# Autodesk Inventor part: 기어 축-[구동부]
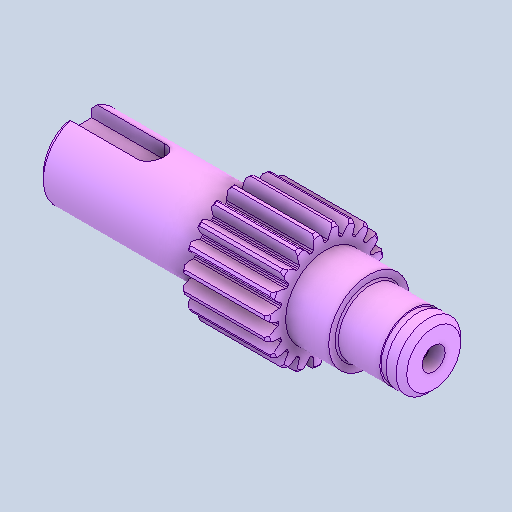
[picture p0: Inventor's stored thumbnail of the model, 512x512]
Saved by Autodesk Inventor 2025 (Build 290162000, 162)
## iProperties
Created: 2026-07
Part Number: 기어 축-[구동부]
Material: 일반
Document SubType Name: Modeling
Designer: KDI
Density: 1 g/cm^3
Appearance: 기본값
Sending System: Autodesk Inventor 2027
Preprocessor: ST-DEVELOPER v20.1
Author: jhkim
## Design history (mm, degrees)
feature "솔리드1"
node "솔리드2"
